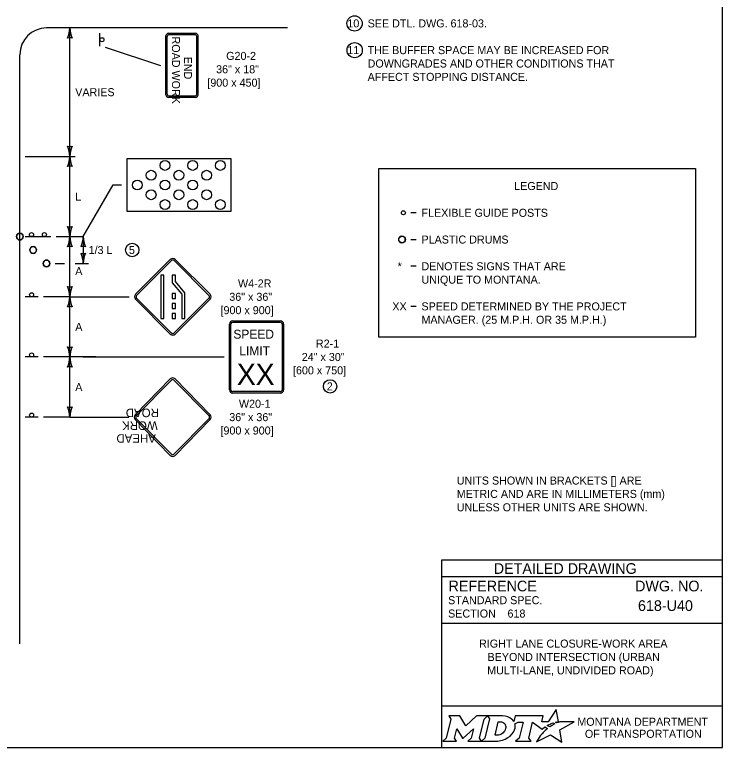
# Model space of a CAD drawing. Extents: x 49991.4 to 50021, y 49987.6 to 50011.4.
# Drawn here: x 50003.32 to 50008.61, y 50000.06 to 50005.54 of the extents above; entities that cross this region are included whole.
import ezdxf

# ---------------------------------------------------------------- set-up
doc = ezdxf.new("R2010")
doc.units = 0
for name, color, linetype in [('Level 1', 7, 'Continuous'), ('Level 2', 7, 'Continuous'), ('Level 3', 7, 'Continuous')]:
    doc.layers.add(name, color=color, linetype=linetype)

msp = doc.modelspace()

# ---------------------------------------------------------------- linework, layer by layer
at = {"layer": 'Level 1'}
for p, q in [((50005.3635, 50005.4426), (50003.5635, 50005.4426)), ((50003.9622, 50005.3066), (50003.9622, 50005.4026)), ((50004.4754, 50005.4026), (50004.6754, 50005.4026)), ((50004.4553, 50004.9427), (50004.4553, 50005.3827)), ((50004.4654, 50004.9476), (50004.4654, 50005.3776)), ((50004.4804, 50005.3926), (50004.6704, 50005.3926)), ((50004.6854, 50004.9476), (50004.6854, 50005.3776)), ((50004.6954, 50004.9426), (50004.6954, 50005.3826)), ((50003.3635, 50000.8367), (50003.3635, 50005.2426)), ((50004.6754, 50004.9226), (50004.4754, 50004.9226)), ((50004.6704, 50004.9326), (50004.4804, 50004.9326)), ((50003.403, 50003.882), (50003.499, 50003.882)), ((50003.499, 50003.882), (50003.595, 50003.882)), ((50004.4882, 50003.7113), (50004.2278, 50003.4505)), ((50004.497, 50003.7025), (50004.2366, 50003.4418)), ((50004.7774, 50003.4418), (50004.5169, 50003.7024)), ((50004.7862, 50003.4506), (50004.5256, 50003.7112)), ((50004.4398, 50003.5942), (50004.4163, 50003.5942)), ((50004.4163, 50003.5942), (50004.4166, 50003.27)), ((50004.44, 50003.27), (50004.4398, 50003.5942)), ((50004.5264, 50003.5943), (50004.503, 50003.5942)), ((50004.503, 50003.5942), (50004.503, 50003.5371)), ((50004.5265, 50003.5457), (50004.5264, 50003.5943)), ((50004.5976, 50003.4619), (50004.5265, 50003.5457)), ((50004.503, 50003.5371), (50004.574, 50003.4527)), ((50003.4995, 50003.432), (50003.4035, 50003.432)), ((50004.5265, 50003.4576), (50004.5031, 50003.4576)), ((50004.5031, 50003.4576), (50004.5031, 50003.42)), ((50004.5266, 50003.42), (50004.5265, 50003.4576)), ((50004.574, 50003.4527), (50004.5741, 50003.2695)), ((50004.5976, 50003.2695), (50004.5976, 50003.4619)), ((50004.2277, 50003.4134), (50004.4883, 50003.1525)), ((50004.2365, 50003.4222), (50004.497, 50003.1612)), ((50004.5031, 50003.42), (50004.5266, 50003.42)), ((50004.5266, 50003.3824), (50004.5031, 50003.3824)), ((50004.5031, 50003.3824), (50004.5032, 50003.3447)), ((50004.5169, 50003.1613), (50004.7775, 50003.4221)), ((50004.5257, 50003.1526), (50004.7863, 50003.4134)), ((50004.5266, 50003.3447), (50004.5266, 50003.3824)), ((50004.5032, 50003.3447), (50004.5266, 50003.3447)), ((50004.4166, 50003.27), (50004.44, 50003.27)), ((50004.5266, 50003.3071), (50004.5032, 50003.3071)), ((50004.5032, 50003.3071), (50004.5032, 50003.2695)), ((50004.5032, 50003.2695), (50004.5267, 50003.2695)), ((50004.5267, 50003.2695), (50004.5266, 50003.3071)), ((50004.5741, 50003.2695), (50004.5976, 50003.2695)), ((50004.9305, 50002.7373), (50004.9305, 50003.2267)), ((50004.941, 50002.7373), (50004.941, 50003.2267)), ((50004.9558, 50003.252), (50005.3102, 50003.252)), ((50004.9558, 50003.2415), (50005.3102, 50003.2415)), ((50005.133, 50003.252), (50005.133, 50003.252)), ((50005.325, 50003.2267), (50005.325, 50002.7373)), ((50005.3356, 50003.2267), (50005.3356, 50002.7373)), ((50003.4995, 50002.982), (50003.4035, 50002.982)), ((50004.2253, 50002.55), (50004.4879, 50002.818)), ((50004.2341, 50002.5414), (50004.4966, 50002.8094)), ((50004.515, 50002.8094), (50004.7776, 50002.5414)), ((50004.5238, 50002.818), (50004.7863, 50002.55)), ((50005.3102, 50002.7225), (50004.9558, 50002.7225)), ((50005.3102, 50002.712), (50004.9558, 50002.712)), ((50003.4995, 50002.532), (50003.4035, 50002.532)), ((50004.4879, 50002.2461), (50004.2253, 50002.5141)), ((50004.4966, 50002.2547), (50004.2341, 50002.5227)), ((50004.7776, 50002.5227), (50004.515, 50002.2547)), ((50004.7863, 50002.5141), (50004.5238, 50002.2461))]:
    msp.add_line(p, q, dxfattribs=at)
for points in [[(50008.6146, 50011.2628), (50000.3356, 50011.2628), (50000.3356, 50000.0624), (50008.6146, 50000.0624)], [(50004.1626, 50004.0733), (50004.9423, 50004.0733), (50004.9423, 50004.4633), (50004.1626, 50004.4633)], [(50004.1626, 50004.0733), (50004.9423, 50004.0733), (50004.9423, 50004.4633), (50004.1626, 50004.4633)]]:
    msp.add_lwpolyline(points, close=True, dxfattribs=at)
for centre, radius in [((50003.9773, 50005.3547), 0.0152), ((50004.4487, 50004.4143), 0.0366), ((50004.4487, 50004.4143), 0.0366), ((50004.6558, 50004.4143), 0.0366), ((50004.6558, 50004.4143), 0.0366), ((50004.8629, 50004.4143), 0.0366), ((50004.8629, 50004.4143), 0.0366), ((50004.3451, 50004.3412), 0.0366), ((50004.3451, 50004.3412), 0.0366), ((50004.5522, 50004.3412), 0.0366), ((50004.5522, 50004.3412), 0.0366), ((50004.7594, 50004.3412), 0.0366), ((50004.7594, 50004.3412), 0.0366), ((50004.2416, 50004.2681), 0.0366), ((50004.2416, 50004.2681), 0.0366), ((50004.4487, 50004.2681), 0.0366), ((50004.4487, 50004.2681), 0.0366), ((50004.6558, 50004.2681), 0.0366), ((50004.6558, 50004.2681), 0.0366), ((50004.3451, 50004.195), 0.0366), ((50004.3451, 50004.195), 0.0366), ((50004.5522, 50004.195), 0.0366), ((50004.5522, 50004.195), 0.0366), ((50004.7594, 50004.195), 0.0366), ((50004.7594, 50004.195), 0.0366), ((50004.4487, 50004.1219), 0.0366), ((50004.4487, 50004.1219), 0.0366), ((50004.6558, 50004.1219), 0.0366), ((50004.6558, 50004.1219), 0.0366), ((50004.8629, 50004.1219), 0.0366), ((50004.8629, 50004.1219), 0.0366), ((50006.2307, 50004.0603), 0.015), ((50003.363, 50003.882), 0.025), ((50003.451, 50003.8972), 0.0152), ((50003.547, 50003.8972), 0.0152), ((50006.2207, 50003.8603), 0.025), ((50003.4629, 50003.782), 0.025), ((50003.5629, 50003.682), 0.025), ((50003.4514, 50003.4471), 0.0152), ((50003.4514, 50002.9971), 0.0152), ((50003.4514, 50002.5471), 0.0152)]:
    msp.add_circle(centre, radius, dxfattribs=at)
for centre, radius, start, end in [((50003.5635, 50005.2426), 0.2, 90, 180), ((50004.4754, 50005.3827), 0.02, 90, 180), ((50004.6754, 50005.3826), 0.02, 360, 90), ((50004.4804, 50005.3776), 0.015, 90, 180), ((50004.6704, 50005.3776), 0.015, 360, 90), ((50004.4754, 50004.9427), 0.02, 180, 270), ((50004.4804, 50004.9476), 0.015, 180, 270), ((50004.6704, 50004.9476), 0.015, 270, 360), ((50004.6754, 50004.9426), 0.02, 270, 360), ((50003.363, 50003.882), 0.025, 0, 180), ((50003.363, 50003.882), 0.025, 180, 0), ((50006.2198, 50003.8603), 0.025, 360, 180), ((50006.2198, 50003.8603), 0.025, 180, 0), ((50003.4629, 50003.782), 0.025, 0, 180), ((50003.4629, 50003.782), 0.025, 180, 0), ((50003.5629, 50003.682), 0.025, 0, 180), ((50004.507, 50003.6926), 0.0263, 45.0001, 134.9999), ((50004.5069, 50003.6927), 0.0139, 45.0001, 134.9999), ((50003.5629, 50003.682), 0.025, 180, 0), ((50004.2462, 50003.432), 0.0263, 134.9999, 225.0001), ((50004.2462, 50003.432), 0.0139, 134.9999, 225.0001), ((50004.7676, 50003.432), 0.0139, 314.9999, 45.0001), ((50004.7676, 50003.432), 0.0263, 314.9999, 45.0001), ((50004.9558, 50003.2267), 0.0253, 90, 180), ((50004.9558, 50003.2267), 0.0148, 90, 180), ((50005.3102, 50003.2267), 0.0253, 0, 90), ((50005.3102, 50003.2267), 0.0148, 0, 90), ((50004.5069, 50003.1713), 0.0139, 225.0001, 314.9999), ((50004.5069, 50003.1713), 0.0263, 225.0001, 314.9999), ((50004.9558, 50002.7373), 0.0253, 180, 270), ((50004.9558, 50002.7373), 0.0148, 180, 270), ((50005.3102, 50002.7373), 0.0148, 270, 360), ((50005.3102, 50002.7373), 0.0253, 270, 360)]:
    msp.add_arc(centre, radius, start, end, dxfattribs=at)
for centre, major_axis, ratio, start_param, end_param in [((50004.5058, 50002.7999), (0, 0.0255), 0.98963, 5.497787, 7.068583), ((50004.5058, 50002.7999), (0, 0.0132), 0.98, 5.497787, 7.068583), ((50004.2432, 50002.532), (0, 0.0255), 0.98963, 0.785394, 2.356194), ((50004.2432, 50002.532), (0, 0.0132), 0.98, 0.785394, 2.356194), ((50004.7684, 50002.532), (0, 0.0132), 0.98, 3.926991, 5.497787), ((50004.7684, 50002.532), (0, 0.0255), 0.98963, 3.926991, 5.497787), ((50004.5058, 50002.264), (0, -0.0255), 0.98963, 5.497795, 7.068583), ((50004.5058, 50002.264), (0, -0.0132), 0.98, 5.497795, 7.068583)]:
    msp.add_ellipse(centre, major_axis=major_axis, ratio=ratio, start_param=start_param, end_param=end_param, dxfattribs=at)
at = {"layer": 'Level 2'}
for p, q in [((50006.0479, 50003.1303), (50006.0479, 50004.3903)), ((50006.3257, 50004.0603), (50006.2857, 50004.0603)), ((50006.2857, 50003.8603), (50006.3257, 50003.8603)), ((50006.3257, 50003.6603), (50006.2857, 50003.6603)), ((50006.3257, 50003.3603), (50006.2857, 50003.3603)), ((50008.4146, 50003.1303), (50006.0479, 50003.1303)), ((50008.6146, 50001.4624), (50006.5146, 50001.4624)), ((50006.5146, 50001.4624), (50006.5146, 50000.0624)), ((50008.6146, 50001.3374), (50006.5146, 50001.3374)), ((50008.2507, 50001.1223), (50008.2507, 50001.1223)), ((50007.0089, 50001.0629), (50007.0089, 50001.0629)), ((50008.6146, 50000.9874), (50006.5146, 50000.9874)), ((50007.5646, 50000.7383), (50007.5646, 50000.7383)), ((50008.6146, 50000.3693), (50006.5146, 50000.3693))]:
    msp.add_line(p, q, dxfattribs=at)
for points in [[(50006.0479, 50004.3903), (50008.4146, 50004.3903), (50008.4146, 50003.1303)], [(50007.3771, 50000.2447), (50007.3668, 50000.2503), (50007.3784, 50000.2531), (50007.39, 50000.2551), (50007.3726, 50000.3452), (50007.3131, 50000.2539), (50007.2658, 50000.2532), (50007.2761, 50000.2973), (50007.0669, 50000.2974), (50007.0568, 50000.2549), (50007.051, 50000.2632)], [(50006.5701, 50000.2974), (50006.5842, 50000.274), (50006.5507, 50000.1307), (50006.525, 50000.1082), (50006.6266, 50000.1082), (50006.6131, 50000.131), (50006.6293, 50000.2011), (50006.673, 50000.1321), (50006.6783, 50000.1321), (50006.7534, 50000.2016), (50006.737, 50000.1305), (50006.7123, 50000.1085), (50006.8139, 50000.1085), (50006.8001, 50000.1318), (50006.8333, 50000.2742)], [(50006.8333, 50000.2742), (50006.8586, 50000.2974), (50006.7762, 50000.2974), (50006.6966, 50000.2244), (50006.6521, 50000.2971), (50006.5701, 50000.2974)], [(50006.9722, 50000.2974), (50006.8586, 50000.2974), (50006.8733, 50000.2745), (50006.8394, 50000.1307), (50006.8139, 50000.1085), (50006.9245, 50000.1085)], [(50006.9962, 50000.2107), (50006.995, 50000.2026), (50006.9918, 50000.1933), (50006.9876, 50000.1851), (50006.982, 50000.1776), (50006.9755, 50000.1707), (50006.9676, 50000.1644), (50006.9593, 50000.1597), (50006.9502, 50000.1558), (50006.9411, 50000.1535), (50006.9319, 50000.1526), (50006.916, 50000.1526), (50006.9396, 50000.2526), (50006.9556, 50000.2526), (50006.9632, 50000.252), (50006.9708, 50000.2501), (50006.9774, 50000.2471), (50006.9835, 50000.2429), (50006.9883, 50000.2379), (50006.992, 50000.2319), (50006.9947, 50000.2257), (50006.9963, 50000.2183), (50006.9963, 50000.2153), (50006.9962, 50000.2107)], [(50007.0636, 50000.2383), (50007.0882, 50000.2514), (50007.1251, 50000.2514), (50007.0965, 50000.1309), (50007.069, 50000.1082), (50007.1852, 50000.1082), (50007.1682, 50000.1311), (50007.1964, 50000.2513), (50007.2677, 50000.1996), (50007.2888, 50000.2147), (50007.3085, 50000.2038)], [(50007.2527, 50000.1479), (50007.2374, 50000.1235), (50007.2327, 50000.116), (50007.2269, 50000.1074), (50007.2246, 50000.1031), (50007.3299, 50000.1562), (50007.4138, 50000.1011), (50007.4007, 50000.1938), (50007.5076, 50000.2522), (50007.4583, 50000.253), (50007.4282, 50000.2534), (50007.4074, 50000.2537), (50007.4006, 50000.2522), (50007.3957, 50000.251), (50007.3873, 50000.2487), (50007.3771, 50000.2447)], [(50007.3267, 50000.2171), (50007.3243, 50000.2154), (50007.306, 50000.225), (50007.3163, 50000.2307), (50007.3204, 50000.2329), (50007.329, 50000.2369), (50007.3347, 50000.2395), (50007.3426, 50000.2425), (50007.3499, 50000.2452), (50007.3617, 50000.2378), (50007.3577, 50000.2357), (50007.3531, 50000.2332), (50007.3489, 50000.231), (50007.3439, 50000.2281), (50007.342, 50000.227), (50007.3393, 50000.2254), (50007.3368, 50000.224), (50007.3345, 50000.2224), (50007.3319, 50000.2206), (50007.3292, 50000.2188), (50007.3267, 50000.2171)], [(50007.2666, 50000.164), (50007.2666, 50000.164)], [(50006.9702, 50000.1158), (50006.9786, 50000.1184), (50006.9916, 50000.1238), (50007.012, 50000.1348)]]:
    msp.add_lwpolyline(points, dxfattribs=at)
for centre, radius in [((50005.8655, 50005.4767), 0.0569), ((50005.8663, 50005.2767), 0.0569), ((50004.2037, 50003.782), 0.0501), ((50005.6831, 50002.762), 0.0501)]:
    msp.add_circle(centre, radius, dxfattribs=at)
for centre, radius, start, end in [((50006.9953, 50000.219), 0.0709, 339.5329, 15.8582), ((50006.9513, 50000.2363), 0.1183, 300.9103, 339.1383)]:
    msp.add_arc(centre, radius, start, end, dxfattribs=at)
for centre, major_axis, ratio, start_param, end_param in [((50006.9701, 50000.25), (0.0834, -0.0037), 0.568097, 0.61298, 1.570796), ((50007.0257, 50000.2573), (0.0361, -0.0295), 0.469099, 1.225588, 1.570796), ((50007.2974, 50000.1941), (-0.0112, -0.0097), 0.021651, 3.157348, 6.283185), ((50007.2597, 50000.1559), (-0.00694, -0.00806), 0.008222, 0, 3.137361), ((50007.2764, 50000.1742), (-0.0098, -0.0102), 0.016458, 3.141593, 6.279097), ((50006.9248, 50000.2568), (0, 0.1484), 0.987302, 3.139398, 3.456847)]:
    msp.add_ellipse(centre, major_axis=major_axis, ratio=ratio, start_param=start_param, end_param=end_param, dxfattribs=at)
at = {"layer": 'Level 3'}
for p, q in [((50003.7377, 50004.482), (50003.7377, 50005.4426)), ((50004.0014, 50005.2988), (50004.4153, 50005.1627)), ((50003.4035, 50004.482), (50003.7777, 50004.482)), ((50003.7377, 50003.882), (50003.7377, 50004.482)), ((50003.8377, 50003.882), (50004.0611, 50004.2683)), ((50004.0611, 50004.2683), (50004.1226, 50004.2683)), ((50003.635, 50003.882), (50003.8377, 50003.882)), ((50003.7377, 50003.432), (50003.7377, 50003.882)), ((50003.8377, 50003.882), (50003.8377, 50003.682)), ((50003.6279, 50003.682), (50003.6977, 50003.682)), ((50003.7777, 50003.682), (50003.8777, 50003.682)), ((50003.7377, 50003.432), (50003.5395, 50003.432)), ((50003.7377, 50003.432), (50003.8377, 50003.432)), ((50003.7377, 50002.982), (50003.7377, 50003.432)), ((50003.8377, 50003.432), (50004.1799, 50003.432)), ((50003.9319, 50002.982), (50003.5395, 50002.982)), ((50003.7377, 50002.532), (50003.7377, 50002.982)), ((50003.8377, 50002.982), (50004.8905, 50002.982)), ((50003.7377, 50002.532), (50003.5395, 50002.532)), ((50003.7377, 50002.532), (50003.8377, 50002.532)), ((50003.8333, 50002.532), (50004.178, 50002.532))]:
    msp.add_line(p, q, dxfattribs=at)
for centre, radius, start, end in [((50003.5156, 50005.4518), 0.2223, 337.456, 357.6395), ((50003.9704, 50005.4541), 0.233, 182.8273, 202.0772), ((50003.7377, 50005.3144), 0.0548, 72.1388, 107.8612), ((50003.7377, 50004.6102), 0.0548, 252.1388, 287.8612), ((50003.505, 50004.4705), 0.233, 2.8273, 22.0772), ((50003.9599, 50004.4728), 0.2223, 157.456, 177.6395), ((50003.5156, 50004.4911), 0.2223, 337.456, 357.6395), ((50003.9704, 50004.4935), 0.233, 182.8273, 202.0772), ((50003.7377, 50004.3538), 0.0548, 72.1388, 107.8612), ((50003.7377, 50004.0102), 0.0548, 252.1388, 287.8612), ((50003.505, 50003.8705), 0.233, 2.8273, 22.0772), ((50003.9599, 50003.8728), 0.2223, 157.456, 177.6395), ((50003.5156, 50003.8911), 0.2223, 337.456, 357.6395), ((50003.9704, 50003.8935), 0.233, 182.8273, 202.0772), ((50003.6156, 50003.8911), 0.2223, 337.456, 357.6395), ((50004.0704, 50003.8935), 0.233, 182.8273, 202.0772), ((50003.7377, 50003.7538), 0.0548, 72.1388, 107.8612), ((50003.8377, 50003.7538), 0.0548, 72.1388, 107.8612), ((50003.8377, 50003.8102), 0.0548, 252.1388, 287.8612), ((50003.605, 50003.6705), 0.233, 2.8273, 22.0772), ((50004.0599, 50003.6728), 0.2223, 157.456, 177.6395), ((50003.7377, 50003.5602), 0.0548, 252.1388, 287.8612), ((50003.505, 50003.4205), 0.233, 2.8273, 22.0772), ((50003.9599, 50003.4228), 0.2223, 157.456, 177.6395), ((50003.5156, 50003.4411), 0.2223, 337.456, 357.6395), ((50003.9704, 50003.4435), 0.233, 182.8273, 202.0772), ((50003.7377, 50003.3038), 0.0548, 72.1388, 107.8612), ((50003.7377, 50003.1102), 0.0548, 252.1388, 287.8612), ((50003.505, 50002.9705), 0.233, 2.8273, 22.0772), ((50003.9599, 50002.9728), 0.2223, 157.456, 177.6395), ((50003.5156, 50002.9911), 0.2223, 337.456, 357.6395), ((50003.9704, 50002.9935), 0.233, 182.8273, 202.0772), ((50003.7377, 50002.8538), 0.0548, 72.1388, 107.8612), ((50003.7377, 50002.6602), 0.0548, 252.1388, 287.8612), ((50003.505, 50002.5205), 0.233, 2.8273, 22.0772), ((50003.9599, 50002.5228), 0.2223, 157.456, 177.6395)]:
    msp.add_arc(centre, radius, start, end, dxfattribs=at)

# ---------------------------------------------------------------- texts
at = {"layer": 'Level 1'}
for s, height, rotation, p in [('ROAD WORK', 0.06, 270, (50004.5007, 50005.3785)), ('END', 0.06, 270, (50004.5907, 50005.2278)), ('ROAD', 0.06389, 180, (50004.4027, 50002.5959)), ('WORK', 0.06389, 180, (50004.3937, 50002.5001)), ('AHEAD', 0.06389, 180, (50004.3801, 50002.4043))]:
    msp.add_text(s, height=height, rotation=rotation, dxfattribs=at).set_placement(p)
for s, height, p in [('SPEED', 0.06695, (50004.9599, 50003.1188)), ('LIMIT', 0.06695, (50005.0043, 50002.995)), ('XX', 0.15772, (50004.9859, 50002.773))]:
    msp.add_text(s, height=height, dxfattribs=at).set_placement(p)
at = {"layer": 'Level 2'}
for s, height, p in [('10', 0.06, (50005.8116, 50005.4467)), ('SEE DTL. DWG. 618-03.', 0.06, (50005.9633, 50005.4467)), ('11', 0.06, (50005.8109, 50005.2467)), ('THE BUFFER SPACE MAY BE INCREASED FOR ', 0.06, (50005.9633, 50005.2467)), ('G20-2', 0.06, (50004.906, 50005.2036)), ('DOWNGRADES AND OTHER CONDITIONS THAT ', 0.06, (50005.9633, 50005.1467)), ('36" x 18"', 0.06, (50004.8308, 50005.1036)), ('AFFECT STOPPING DISTANCE. ', 0.06, (50005.9633, 50005.0467)), ('[900 x 450]', 0.06, (50004.7652, 50005.0036)), ('VARIES', 0.06, (50003.7777, 50004.9323)), ('LEGEND', 0.06, (50007.0587, 50004.2303)), ('L', 0.06, (50003.7777, 50004.152)), ('FLEXIBLE GUIDE POSTS', 0.06, (50006.3657, 50004.0303)), ('PLASTIC DRUMS', 0.06, (50006.3657, 50003.8303)), ('1/3 L', 0.06, (50003.8777, 50003.752)), ('5', 0.06, (50004.1788, 50003.752)), ('*', 0.06, (50006.1871, 50003.6303)), ('DENOTES SIGNS THAT ARE', 0.06, (50006.3657, 50003.6303)), ('W4-2R', 0.06, (50004.9944, 50003.502)), ('UNIQUE TO MONTANA.', 0.06, (50006.3657, 50003.5303)), ('36" x 36"', 0.06, (50004.9293, 50003.402)), ('XX', 0.06, (50006.1479, 50003.3303)), ('SPEED DETERMINED BY THE PROJECT', 0.06, (50006.3657, 50003.3303)), ('[900 x 900]', 0.06, (50004.8637, 50003.302)), ('MANAGER. (25 M.P.H. OR 35 M.P.H.)', 0.06, (50006.3657, 50003.2303)), ('R2-1', 0.06, (50005.5766, 50003.052)), ('24" x 30"', 0.06, (50005.471, 50002.952)), ('[600 x 750]', 0.06, (50005.4054, 50002.852)), ('2', 0.06, (50005.6579, 50002.732)), ('W20-1', 0.06, (50005.0013, 50002.602)), ('36" x 36"', 0.06, (50004.9291, 50002.502)), ('[900 x 900]', 0.06, (50004.8635, 50002.402)), ('UNITS SHOWN IN BRACKETS [] ARE ', 0.06, (50006.6294, 50002.0278)), ('METRIC AND ARE IN MILLIMETERS (mm) ', 0.06, (50006.6294, 50001.9278)), ('UNLESS OTHER UNITS ARE SHOWN.', 0.06, (50006.6294, 50001.8278)), ('DETAILED DRAWING', 0.0799, (50006.9063, 50001.3599)), ('REFERENCE', 0.08, (50006.5682, 50001.229)), ('DWG. NO.', 0.08, (50007.9624, 50001.229)), ('STANDARD SPEC.', 0.06, (50006.5649, 50001.133)), ('618-U40', 0.08, (50007.9841, 50001.0823)), ('SECTION', 0.06, (50006.5649, 50001.033)), ('618', 0.06, (50007.0089, 50001.0329)), (' RIGHT LANE CLOSURE-WORK AREA', 0.06, (50006.7737, 50000.8083)), ('BEYOND INTERSECTION (URBAN ', 0.06, (50006.8594, 50000.7083)), ('MULTI-LANE, UNDIVIDED ROAD)', 0.06, (50006.8567, 50000.6083)), ('MONTANA DEPARTMENT', 0.06, (50007.5308, 50000.2236)), ('OF TRANSPORTATION', 0.06, (50007.587, 50000.1336))]:
    msp.add_text(s, height=height, dxfattribs=at).set_placement(p)
for p in [(50003.7777, 50003.5947), (50003.7777, 50003.177), (50003.7777, 50002.727)]:
    msp.add_text('A', height=0.06, rotation=360, dxfattribs=at).set_placement(p)

doc.saveas('drawing.dxf')
